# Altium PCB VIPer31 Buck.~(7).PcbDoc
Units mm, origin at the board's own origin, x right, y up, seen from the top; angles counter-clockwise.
Board outline 152.4 x 101.6 mm, 2 copper layers (Top Layer, Bottom Layer); 31 components, 16 nets, 72 pads, 0 vias.
Unrouted connection lines stored in the file: 4.
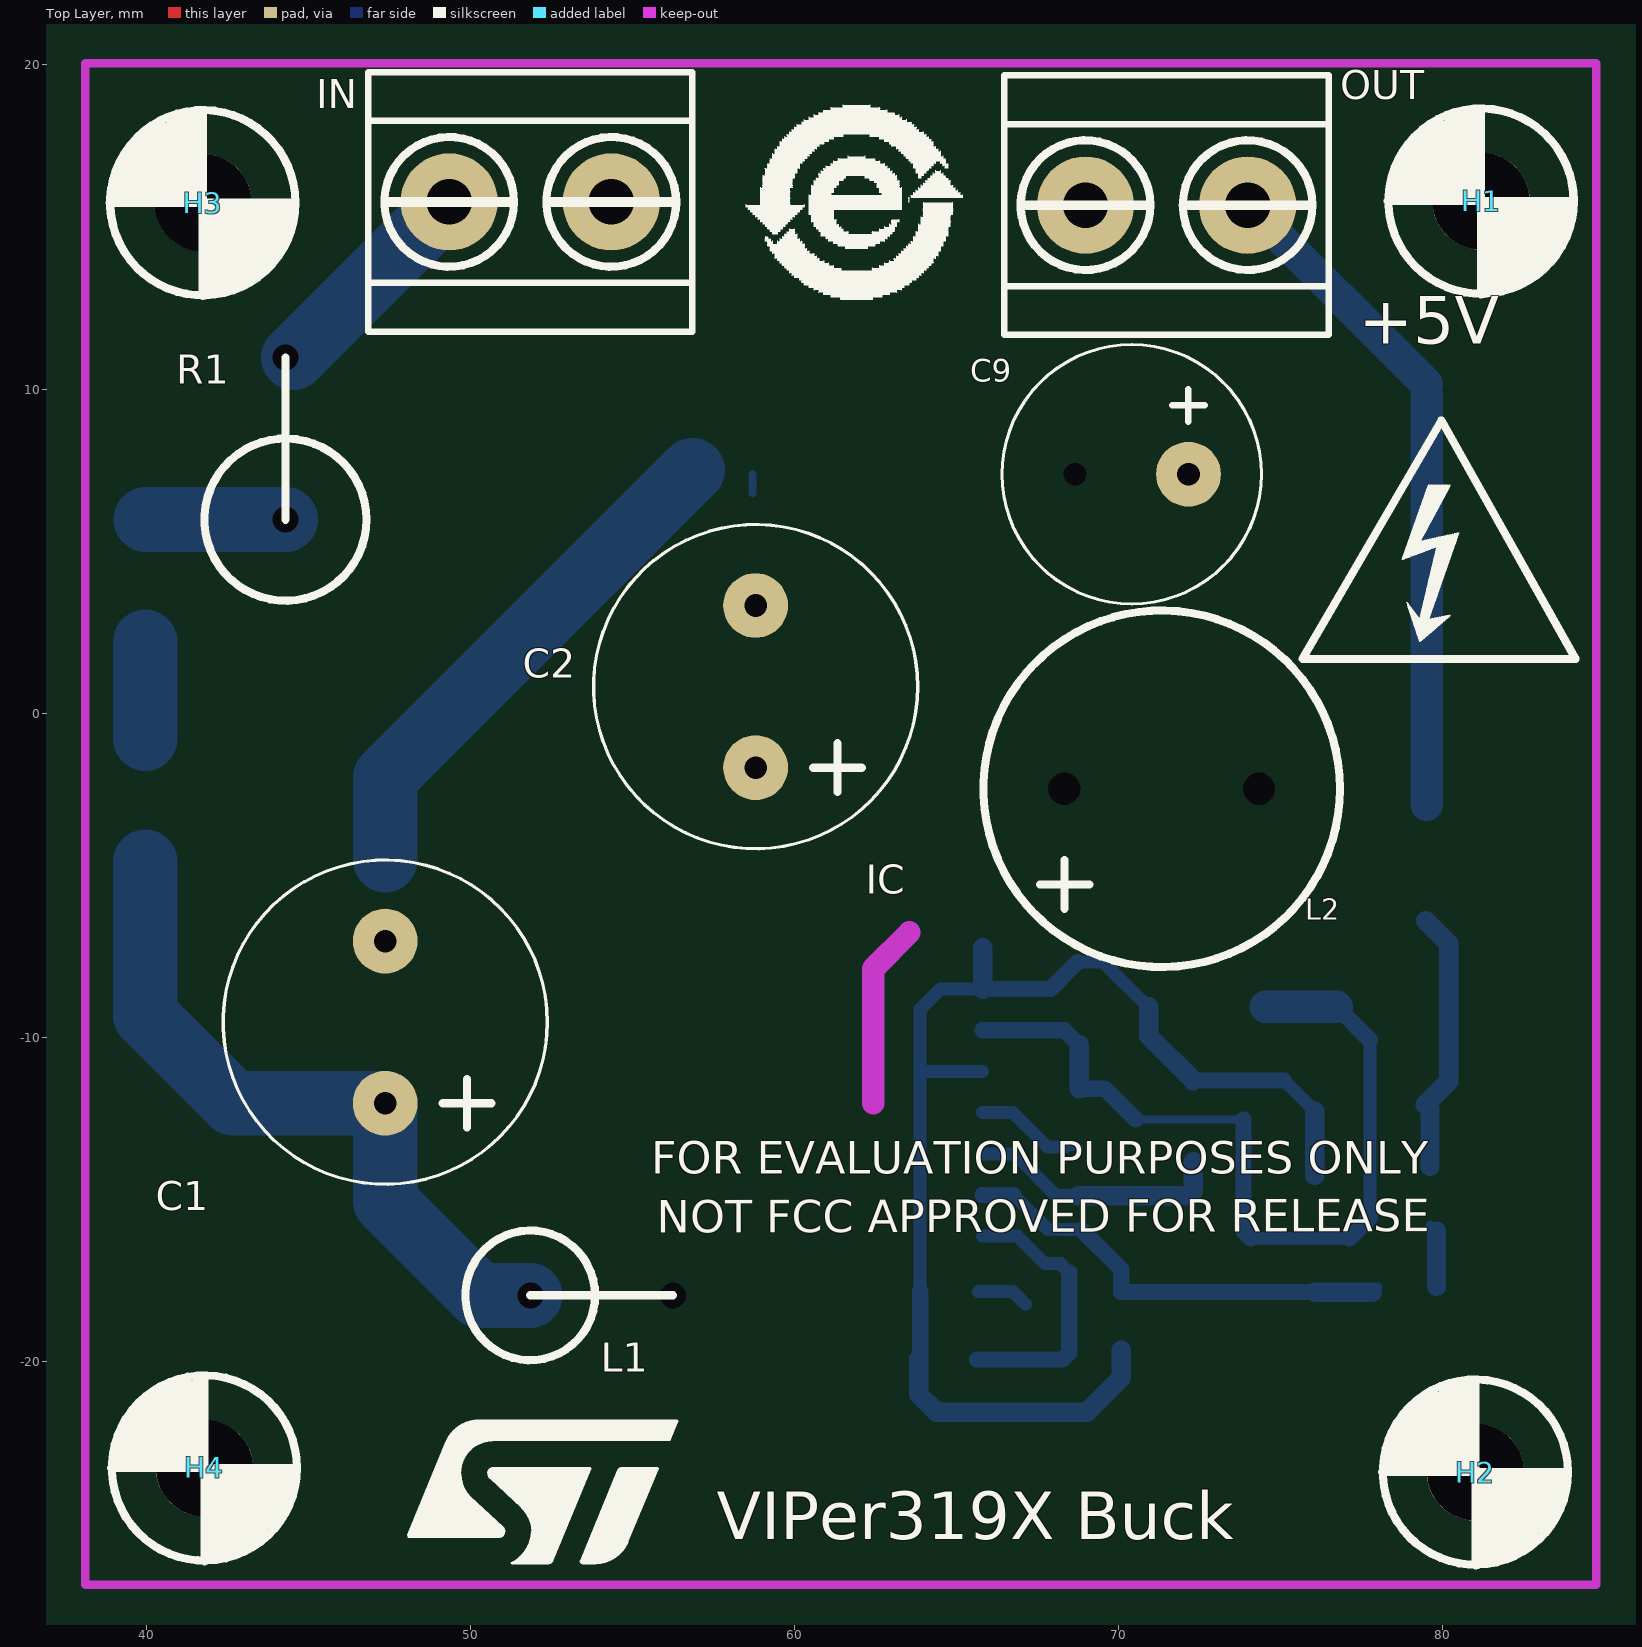
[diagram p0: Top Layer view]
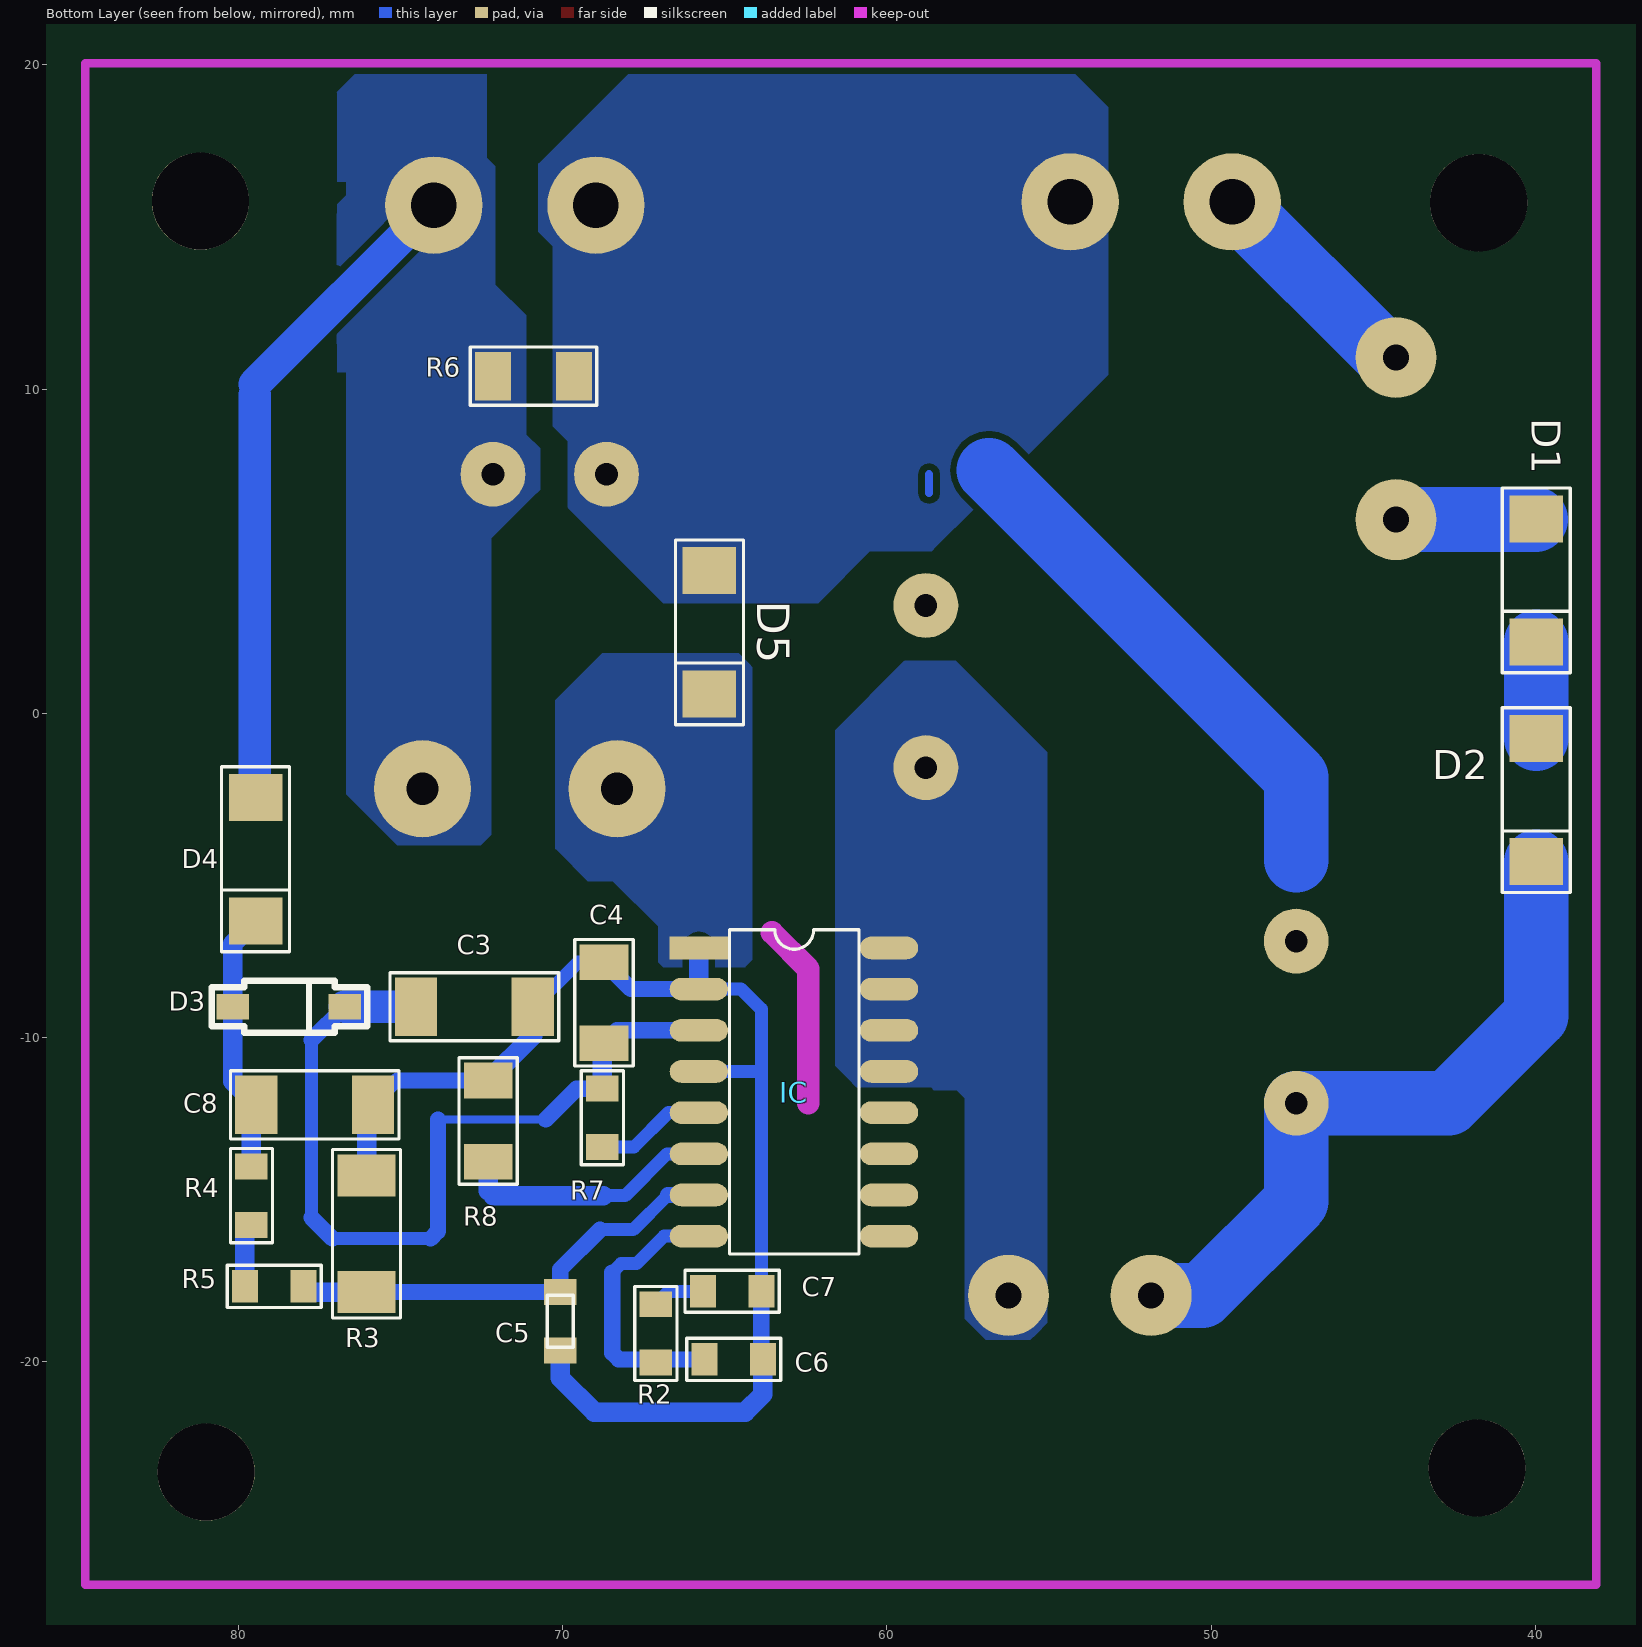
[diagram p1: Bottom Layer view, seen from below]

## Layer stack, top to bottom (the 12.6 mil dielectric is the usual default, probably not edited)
Top Solder: solder mask 0.0102, Solder Resist, Dk 3.5
Top Layer: signal copper 0.0356
Dielectric 1: dielectric 0.32, FR-4, Dk 4.8
Bottom Layer: signal copper 0.0356
Bottom Solder: solder mask 0.0102, Solder Resist, Dk 3.5

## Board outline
-0.1,-51.05 152.3,-51.05 152.3,50.55 -0.1,50.55

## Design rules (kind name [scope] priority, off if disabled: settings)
Clearance Clearance_1 [All] p1: gap=0.2 ignorepadtopadclearanceinfootprint=FALSE except(0: Arc-Hole Track-Hole SMDPad-Hole THPad-Hole Via-Hole Fill-Hole Poly-Hole Region-Hole Text-Hole)
Clearance [All] p2: gap=0.254 ignorepadtopadclearanceinfootprint=FALSE except(0: Arc-Poly Arc-Hole Track-Poly Track-Region Track-Hole SMDPad-Poly SMDPad-Hole THPad-Poly THPad-Hole Via-Poly Via-Hole Fill-Poly Fill-Hole Poly-Poly Poly-Hole Region-Hole Text-Hole)
PolygonConnect [All] p1: connectstyle=Direct reliefconductorwidth=0.254 reliefentries=4 polygonreliefangle="90 Angle" airgapwidth=0.254
RoutingVias [All] p1: holewidth=0.711 width=1.27 viastyle="Through Hole" minholewidth=0.711 minwidth=1.27 maxholewidth=0.711 maxwidth=1.27
SolderMaskExpansion [All] p1: expansion=0.102
Width [All] p1: maxlimit=2 minlimit=0.254 preferedwidth=0.254 minimp=50.000000 maximp=50.000000 favimp=50.000000
30 further rules are at their usual default settings.

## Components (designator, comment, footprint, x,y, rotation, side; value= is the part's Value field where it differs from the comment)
C1 "22 uF 400 Vcc" CAPOL-5X10 47.375,-12.025 r90 top value="68 uF +/-20%, 400 Vcc, +105°C"
C2 "22 uF 400 Vcc" CAPOL-5X10 58.8,-1.675 r90 top value="68 uF +/-20%, 400 Vcc, +105°C"
C3 "4.7uF 50V" R-1206-B2 74.525,-9.05 r180 top value="1 nF 630 Vdc"
C4 "100pF" R-0805-B2 68.725,-10.175 r90 top value="100 pF +/-5%, 250 Vdc"
C5 "n.c." R-0603-B 70.075,-19.65 r90 top value=100pF
C6 "tbd" R-0603-B2 65.625,-19.925 r180 top value="1 nF +/-5%, 200 Vdc"
C7 "tbd" R-0603-B2 65.675,-17.825 r180 top
C8 "220 nF" R-1206-B2 79.45,-12.075 r180 top value="100nF ±10%, 25 Vcc"
C9 "680 uF, 25 Vcc" CAPOL-3.5X8 72.15,7.375 r180 top value="470 uF +/-20%, 35 Vcc, +105°C"
D1 "MRA4007" SMA-2 39.975,6 r90 top
D2 "MRA4007" SMA-2 39.975,-0.775 r90 top
D3 "BAT46ZFILM" SOD-123 80.175,-9.05 r0 top value=MRA4007T3G
D4 "STTH1L06" SMA-2 79.475,-2.6 r90 top value="1 A, 150 V"
D5 "STTH1L06" SMA-2 65.475,4.4 r90 top value="Schottky diode, 10A, 200 V"
H1 "HOLE" FORO 81.175,15.8 r0 top
H2 "HOLE" FORO 81,-23.4 r0 top
H3 "HOLE" FORO 41.75,15.75 r0 top
H4 "HOLE" FORO 41.8,-23.275 r0 top
IC "VIPER31_SO16" SO-16N_2 65.8,-7.235 r270 top
IN "input connector" SM.2VITE 54.35,15.775 r180 top
L1 "1mH" 1W-VER 51.85,-17.95 r0 top value="3.3UH 3.23A 33 MOHM"
L2 "270uH" CAPOL-6X11 68.325,-2.325 r0 top value="3.3UH 3.23A 33 MOHM"
OUT "output connector" SM.2VITE 73.975,15.675 r180 top
R1 "10 Ohm" 2W-VER 44.3,5.975 r90 top
R2 "tbd" R-0603-B2 67.125,-18.225 r270 top
R3 "22k" R-1206-B2 76.05,-14.25 r270 top value="0 Ohm, 0.25W"
R4 "22k" R-0603-B2 79.6,-15.775 r90 top
R5 "56k" R-0603-B2 79.8,-17.675 r180 top
R6 "5.6 kOhm" R-0805-B2 69.65,10.4 r0 top value="1MOhm +/-5%"
R7 "0" R-0603-B2 68.775,-11.575 r270 top
R8 "Res1" R-0805-B2 72.3,-11.325 r270 top value=0

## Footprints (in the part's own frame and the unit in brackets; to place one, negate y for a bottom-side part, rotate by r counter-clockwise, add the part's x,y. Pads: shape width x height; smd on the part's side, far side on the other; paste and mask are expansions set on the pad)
1W-VER [mm]
  round 0 / inner round 0 / far side round 2.5 hole 0.8: 1(0,0) 2(4.4,0)
  silkscreen extent -2,-2 4.4,2
2W-VER [mm]
  round 0 / inner round 0 / far side round 2.5 hole 0.8: 1(0,0) 2(5,0)
  silkscreen extent -2.5,-2.5 5,2.5
CAPOL-3.5X8 [mm]
  round 2 hole 0.7: 1(0,0)
  round 0 / inner round 0 / far side round 2 hole 0.7: 2(3.5,0)
  silkscreen extent -2.25,-4 5.75,4
CAPOL-5X10 [mm]
  round 2 hole 0.7: 1(0,0) 2(5,0)
  silkscreen extent -2.5,-5 7.5,5
CAPOL-6X11 [mm]
  round 0 / inner round 0 / far side round 3 hole 1: 1(0,0) 2(6,0)
  silkscreen extent -2.5,-5.5 8.5,5.5
FORO [mm]
  round 3 hole 3: 1(0,0)
  silkscreen extent -2.88,-2.88 2.86,2.86
R-0603-B [mm]
  rect 0.8x1 smd far side: 1(0,0) 2(1.8,0)
R-0603-B2 [mm]
  rect 0.8x1 smd far side: 1(0,0) 2(1.8,0)
R-0805-B2 [mm]
  rect 1.1x1.5 smd far side: 1(0,0) 2(2.5,0)
R-1206-B2 [mm]
  rect 1.3x1.8 smd far side: 1(0,0) 2(3.6,0)
SM.2VITE [mm]
  round 3 hole 1.4: 1(0,0) 2(5,0)
  silkscreen extent -2.5,-4 7.5,4
SMA-2 [mm]
  rect 1.45x1.65 smd far side: 1(0,0) 2(-3.8,0)
SO-16N_2 [mm]
  rect 0.7x1.8 smd far side: 1(0,0)
  oval 0.7x1.8 smd far side: 2(1.27,0) 3(2.54,0) 4(3.81,0) 5(5.08,0) 6(6.35,0) 7(7.62,0) 8(8.89,0) 9(8.89,-5.864) 10(7.62,-5.864) 11(6.35,-5.864) 12(5.08,-5.864) 13(3.81,-5.864) 14(2.54,-5.864) 15(1.27,-5.864) 16(0,-5.864)
SOD-123 [mm]
  rect 1x0.8 smd far side: 1(0,0) 2(-3.45,0)

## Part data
C1 C2: library part "Cap Pol1", "Polarized Capacitor (Radial)", Package="TH D{}18 mm, H{}25 mm, P{}7.5 mm", Part number=400BXC68MEFC18X25
C3: library part CAP, "1 nF 630 V multi layer capacitor", Package="SMD 1206", Part number=C3216C0G2J102J085AA
C4: library part CAP, "100 pF 250 Vdc multi layer capacitor", Package="SMD 0603", Part number=CGA3E3C0G2E101J080AA
C5: library part Cap, "Capacitor"
C6: library part CAP, "1 nF 200 Vdc multi layer capacitor", Package="SMD 0603", Part number=C0603C102J2GACAUTO
C7: library part CAP, "NC", Package="SMD 0603"
C8: library part CAP, "100nF ±10%, 25 Vcc, MLCC", Package="SMD 0603", Part number=C0603C104K3RACTU
C9: library part "Cap Pol1", "470 uF +/-20%, 35 Vcc, +105°C", Package="TH D{}10 mm, H{}12.5 mm, P{}5 mm", Part number=25ZLH470MEFC10X12.5
D1 D2: library part "Diode 1N4007", "1 Amp General Purpose Rectifier"
D3: library part Diode, "Silicon Diode, 1 A, 1000 V", Part number=MRA4007T3G
D4: library part Diode, "small signal diode", Part number=STPS1150A
D5: library part Diode, "Schottky diode, 10A, 200 V", Part number=STPS2200UF
IC: "Integrato"
IN OUT: library part M.2VITE, "Morsetti"
L1 L2: library part Inductor, "FIXED IND 3.3UH 3.23A 33 MOHM", Package="Lu x La: 0,157 x 0,157\" (4,00 x 4,00 mm)", Part number=74404043033A
R1: library part Res2, Package="TH 9 mm X 4 mm , P 5mm", Part number=NTPA7100LBMB0
R2 R4 R5: library part Res1, "Not connected", Package="SMD 0603"
R3: library part Res1, "0O, 0.25W, pkg 0603, serie CRCW", Package="SMD 0603", Part number=CRCW06030000Z0EAHP
R6: library part Res1, "6.8 kOhm +/-1% 0.125W, 0805 Panasonic", Package="SMD 1206", Part number=ERJP08J105V
R7: library part Res1, "Resistor"
R8: "Resistor"

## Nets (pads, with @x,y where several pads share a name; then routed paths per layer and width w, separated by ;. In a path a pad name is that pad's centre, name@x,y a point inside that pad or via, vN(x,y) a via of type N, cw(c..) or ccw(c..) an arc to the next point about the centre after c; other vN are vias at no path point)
GND: C1.2 C2.2 C9.2 D5.1 IN.1 OUT.2 R6.1 | length 16.5
  Bottom Layer w0.254: 58.7,6.8 58.7,7.375
  Bottom Layer w2: 47.375,-4.525 47.375,-1.975 56.85,7.5
NetC1_1: C1.1 D2.2 L1.1 | length 22
  Bottom Layer w2: D2.2 39.975,-9.325 42.675,-12.025 C1.1 47.375,-15.05 50.275,-17.95 L1.1
NetC2_1: C2.1 IC.13 IC.14 IC.15 IC.16 L1.2
NetC3_1: C3.1 C4.1 D3.2 IC.3 R7.1 | length 26.8
  Bottom Layer w0.254: C4.1 C4.1@68.775,-10.225 ; 70.525,-12.525 73.85,-12.525
  Bottom Layer w0.4: 74.075,-16.2 77.1,-16.2 ; 77.75,-15.55 77.75,-10.075
  Bottom Layer w0.5: IC.3 68.325,-9.775 C4.1 ; R7.1 69.575,-11.575 70.525,-12.525 ; 73.85,-12.525 73.85,-15.975 74.075,-16.2 ; D3.2 77.75,-10.075 ; 77.1,-16.2 77.75,-15.55
  Bottom Layer w0.6: R7.1 C4.1@68.775,-10.225
  Bottom Layer w1: C3.1 D3.2
NetC3_2: C3.2 C4.2 C5.1 C6.2 C7.2 C8.2 D5.2 IC.1 IC.2 IC.4 L2.1 R3.1 R8.1 | length 40
  Bottom Layer w0.254: C6.2 C6.2@63.875,-19.875 ; 63.875,-11.05 63.88,-11.045 ; C3.2@70.9,-9.05 C3.2 ; C8.2 C8.2@76.05,-12.275
  Bottom Layer w0.4: C7.2@63.875,-17.8 63.875,-11.05 63.875,-9.125 64.495,-8.505 IC.2 ; 63.88,-11.045 IC.4 ; C4.2 69.525,-7.675 C3.2@70.9,-9.05 ; 75.1,-11.325 C8.2
  Bottom Layer w0.5: C6.2@63.875,-19.875 C7.2 ; IC.2 67.895,-8.505 C4.2 ; R8.1 75.1,-11.325
  Bottom Layer w0.6: C6.2 63.825,-21 64.375,-21.55 69.025,-21.55 70.075,-20.5 C5.1 ; IC.2 IC.1 ; C3.2 70.925,-9.95 R8.1 ; R3.1 C8.2@76.05,-12.275
NetC5_2: C5.2 IC.7 R3.2 R5.2 | length 13.9
  Bottom Layer w0.254: R5.2@77.825,-17.85 R5.2
  Bottom Layer w0.4: 66.755,-14.855 67.825,-15.925 68.85,-15.925
  Bottom Layer w0.5: IC.7 66.755,-14.855 ; 68.85,-15.925 70.075,-17.15 C5.2 R3.2
  Bottom Layer w0.6: R3.2 R5.2@77.825,-17.85
NetC6_1: C6.1 IC.8 R2.2 | length 8.5
  Bottom Layer w0.4: IC.8 66.875,-16.125 67.725,-16.975 68.2,-16.975 68.475,-17.25
  Bottom Layer w0.5: C6.1 68.275,-19.925 68.475,-19.725 68.475,-17.25
NetC7_1: C7.1 R2.1 | length 1.6
  Bottom Layer w0.4: C7.1 66.725,-17.825 R2.1
NetC8_1: C8.1 D3.1 D4.2 R4.2 | length 8.2
  Bottom Layer w0.254: C8.1 C8.1@79.6,-12.225
  Bottom Layer w0.6: C8.1 80.175,-11.35 D3.1 80.175,-7.1 D4.2 ; R4.2 C8.1@79.6,-12.225
NetC9_1: C9.1 D4.1 L2.2 OUT.1 R6.2 | length 20.8
  Bottom Layer w0.254: 79.5,9.825 79.5,10.15
  Bottom Layer w1: OUT.1 79.5,10.15 ; D4.1@79.5,-2.825 79.5,9.825
NetD1_1: D1.1 R1.1 | length 4.3
  Bottom Layer w2: D1.1@40,5.975 R1.1
NetD1_2: D1.2 D2.1 | length 3
  Bottom Layer w2: D2.1 D1.2
NetIC_5: IC.5 R7.2 | length 3.4
  Bottom Layer w0.254: R7.2@68.35,-13.375 R7.2
  Bottom Layer w0.4: IC.5 66.74,-12.315 67.8,-13.375 R7.2@68.35,-13.375
NetIC_6: IC.6 R8.2 | length 8
  Bottom Layer w0.254: 72.15,-14.875 72.3,-14.725
  Bottom Layer w0.4: IC.6 66.785,-13.585 68.075,-14.875 68.75,-14.875
  Bottom Layer w0.6: 68.75,-14.875 72.15,-14.875 ; 72.3,-14.725 R8.2
NetIN_2: IN.2 R1.2 | length 7.4
  Bottom Layer w0.254: R1.2 R1.2@44.55,10.975
  Bottom Layer w2: R1.2@44.55,10.975 IN.2 ; IN.2@49.35,15.575 IN.2@49.675,15.575
NetR4_1: R4.1 R5.1 | length 2
  Bottom Layer w0.254: R4.1 R4.1@79.8,-15.975
  Bottom Layer w0.6: R5.1 R4.1@79.8,-15.975
pads on no net: H1.1 H2.1 H3.1 H4.1 IC.9 IC.10 IC.11 IC.12

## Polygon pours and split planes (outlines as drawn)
NetC9_1 on Bottom Layer "Bottom Layer-No Net 1" (solid, pour order 30): 72.2,-3.75 72.525,-4.075 75.1,-4.075 76.675,-2.5 76.675,-0.4 76.275,0 72.375,0 72.375,-0.025 72.2,-0.2
NetC9_1 on Bottom Layer "Bottom Layer-No Net" (solid, remove dead copper, pour order 28): 71.125,10.925 71.125,8.875 71.125,8.6 70.95,8.425 70.7,8.175 70.7,6.9 70.95,6.65 72.2,5.4 72.2,-0.2 72.2,-1.975 72.275,-2.05 72.875,-2.65 74.125,-2.65 74.425,-2.65 75.4,-1.675 76.675,-0.4 76.675,16.05 76.675,16.75 75.425,18 75.275,18.15 73.825,18.15 73.35,18.15 72.95,17.75 72.075,16.875 72.075,16.2 72.075,13.225 71.425,12.575 71.125,12.275 71.125,10.875
NetC9_1 on Bottom Layer "Bottom Layer-No Net 1" (solid, pour order 22): 76.95,10.525 76.95,15.7 76,16.65 73.55,16.65 73.025,16.125 73.025,14.225 76.25,11 76.6,11 76.6,10.7 76.775,10.525
NetC9_1 on Bottom Layer "Bottom Layer-No Net 1" (solid, pour order 20): 76.95,10.525 76.95,15.7 75.1,15.7 74.3,16.5 73.45,16.5 73.45,16.3 73.05,15.9 73.2,15.75 73.2,13.45 76.125,10.525
NetC9_1 on Bottom Layer "Bottom Layer-No Net" (solid, remove dead copper, pour order 18): 76.975,11.4 76.975,15.483 76.95,15.508 76.942,15.5 73.475,15.5 73.475,11.6 73.65,11.425 73.675,11.4 76.95,11.4
NetC9_1 on Bottom Layer "Bottom Layer-No Net" (solid, remove dead copper, pour order 16): 72.35,16.525 72.35,19.85 72.375,19.875 72.4,19.9 74.775,19.9 76.225,19.9 76.975,19.15 76.95,19.125 76.95,16.4 72.575,16.4 72.55,16.375 72.4,16.525 72.35,16.525
NetC2_1 on Bottom Layer "Bottom Layer-No Net" (solid, remove dead copper, pour order 14): 57.6,-18.45 57.6,-11.875 57.8,-11.675 57.85,-11.625 58.3,-11.625 58.55,-11.625 58.625,-11.55 58.65,-11.525 60.675,-11.525 60.95,-11.525 61.2,-11.275 61.6,-10.875 61.6,-2.95 61.6,-0.525 59.475,1.6 59.45,1.625 58.175,1.625 57.875,1.625 56.825,0.575 55.05,-1.2 55.05,-17.125 55.05,-18.8 55.4,-19.15 55.575,-19.325 56.9,-19.325 56.95,-19.325 57.55,-18.725 57.6,-18.675 57.6,-18.45
NetC3_2 on Bottom Layer "Bottom Layer-No Net" (solid, remove dead copper, pour order 12): 64.15,0.725 64.15,-6.725 64.15,-7.6 64.35,-7.8 64.375,-7.825 66.375,-7.825 66.9,-7.825 67.05,-7.675 67.05,-7.425 67.05,-6.575 67.075,-6.55 68.45,-5.175 68.825,-5.175 69.225,-5.175 70.175,-4.225 70.225,-4.175 70.225,-3.025 70.225,0.4 68.775,1.85 64.75,1.85 64.575,1.85 64.25,1.525 64.15,1.425 64.15,0.75
GND on Bottom Layer "Bottom Layer-No Net" (solid, remove dead copper, pour order 8): 53.175,15 53.175,10.45 58.475,5.15 58.625,5 60.1,5 60.525,5 62.075,3.45 62.125,3.4 66.35,3.4 66.9,3.4 69.825,6.325 69.85,6.35 69.85,6.75 69.85,8.4 70.15,8.7 70.3,8.85 70.3,10.15 70.3,14.4 70.375,14.475 70.75,14.85 70.75,15.125 70.75,16.95 70.7,17 67.9,19.8 67.775,19.8 54.275,19.8 54.175,19.7 53.175,18.7 53.175,15

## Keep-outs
Keep-Out Layer:
  lines w0.254: 38.125,-26.875 38.125,20.05 84.725,20.05 84.725,-26.875 38.125,-26.875
  lines w0.7: 62.425,-12.025 62.425,-7.875 63.542,-6.758

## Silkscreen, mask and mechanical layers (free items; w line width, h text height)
Top Overlay:
  drawing of 10878 lines, arcs and shapes, not listed
  text "+5V" at 77.4,10.925 h2.5
  text "FOR EVALUATION PURPOSES ONLY" at 55.575,-14.2 h1
  text "NOT FCC APPROVED FOR RELEASE" at 55.75,-16.025 h1 r0.1
  text "VIPer319X Buck" at 57.6,-25.95 h2.5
